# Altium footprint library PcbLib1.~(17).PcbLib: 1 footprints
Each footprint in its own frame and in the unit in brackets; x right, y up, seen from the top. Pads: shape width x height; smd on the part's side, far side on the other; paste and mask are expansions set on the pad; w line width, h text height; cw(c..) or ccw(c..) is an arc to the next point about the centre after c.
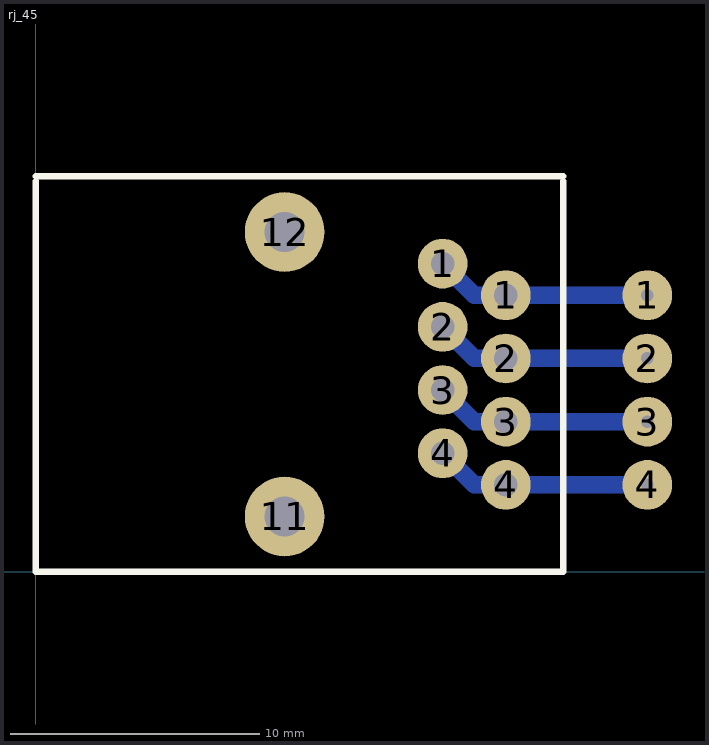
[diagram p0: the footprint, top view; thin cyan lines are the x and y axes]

## rj_45 [mm]
pads (14):
  round 2 hole 0.95: 1(16.35,12.385) 1(18.89,11.115) 2(16.35,9.845) 2(18.89,8.575) 3(16.35,7.305) 3(18.89,6.035) 4(16.35,4.765) 4(18.89,3.495)
  round 2 hole 0.5: 1(24.575,11.115) 2(24.575,8.575) 3(24.575,6.035) 4(24.575,3.495)
  round 3.2 hole 1.6: 11(10,2.225) 12(10,13.655)
Bottom Layer:
  lines w0.7: 16.35,4.765 17.62,3.495 18.89,3.495 24.575,3.495 ; 16.35,7.305 17.62,6.035 18.89,6.035 24.575,6.035 ; 16.35,9.845 17.62,8.575 18.89,8.575 24.575,8.575 ; 16.35,12.385 17.62,11.115 18.89,11.115 24.575,11.115
Top Overlay:
  lines w0.254: 0,15.7 0,0 21.2,0 21.2,15.7 ; 0,15.9 21.2,15.9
